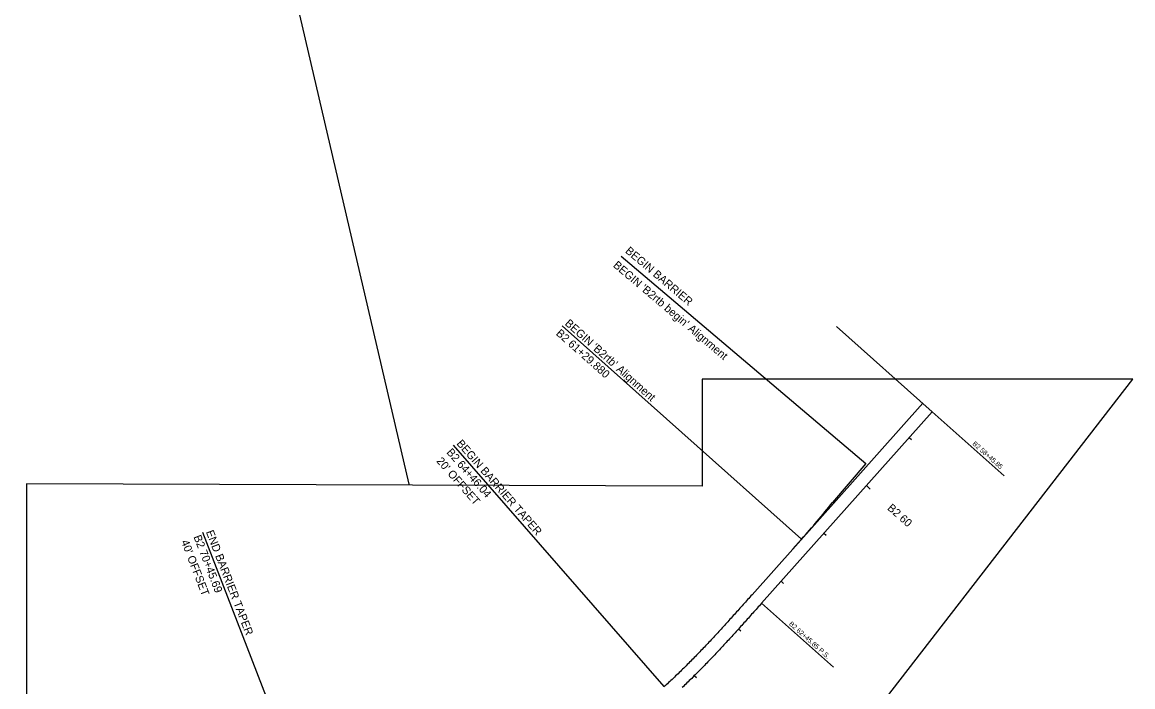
# Model space of a CAD drawing. Extents: x 7583978 to 7589962, y 550226 to 553847.
# Drawn here: x 7588230 to 7589962, y 550949 to 551985 of the extents above; entities that cross this region are included whole.
import ezdxf

# ---------------------------------------------------------------- set-up
doc = ezdxf.new("R2010")
doc.units = 0
for name, color, linetype in [('#plot_shape', 7, 'Continuous'), ('Default', 7, 'Continuous'), ('P_RDWY_ALIGN_Main', 7, 'Continuous'), ('P_RDWY_ALIGN_MainTx', 7, 'Continuous'), ('P_RDWY_ALIGN_Ramp', 7, 'Continuous'), ('P_RDWY_ALIGN_RampTic', 7, 'Continuous'), ('P_RDWY_ALIGN_RampTx', 7, 'Continuous')]:
    doc.layers.add(name, color=color, linetype=linetype)

msp = doc.modelspace()

# ---------------------------------------------------------------- linework, layer by layer
at = {"layer": '#plot_shape'}
msp.add_lwpolyline([(7588834, 551264.9), (7588256.1, 553744.3), (7587181.8, 553744.3)], dxfattribs=at)
msp.add_lwpolyline([(7588237.1, 551265.4), (7588237.1, 550226), (7589430.9, 550226), (7589430.9, 550741.5), (7589962.5, 551428.8), (7589291.1, 551428.4), (7589291.1, 551261.9)], close=True, dxfattribs=at)
at = {"layer": 'Default'}
for p, q in [((7589164.5, 551620.5), (7589546, 551297.3)), ((7589072.6, 551511.8), (7589445.8, 551179)), ((7589231.8, 550949.2), (7588902.8, 551325.7)), ((7588692.7, 550723.1), (7588512.2, 551189.4))]:
    msp.add_line(p, q, dxfattribs=at)
at = {"layer": 'P_RDWY_ALIGN_Main'}
for p, q in [((7589634.8, 551391), (7589368.6, 551092.5)), ((7589546, 551297.3), (7589494.2, 551236.2)), ((7589494.2, 551236.2), (7589494.1, 551236)), ((7589445.7, 551179), (7589432.4, 551164)), ((7589445.8, 551179), (7589445.7, 551179)), ((7589361.7, 551084.8), (7589360, 551082.9)), ((7589363.4, 551086.7), (7589361.7, 551084.8)), ((7589365.2, 551088.6), (7589363.4, 551086.7)), ((7589366.9, 551090.6), (7589365.2, 551088.6)), ((7589368.6, 551092.5), (7589366.9, 551090.6)), ((7589346.3, 551067.5), (7589344.6, 551065.6)), ((7589348, 551069.4), (7589346.3, 551067.5)), ((7589349.7, 551071.4), (7589348, 551069.4)), ((7589351.4, 551073.3), (7589349.7, 551071.4)), ((7589353.1, 551075.2), (7589351.4, 551073.3)), ((7589354.9, 551077.1), (7589353.1, 551075.2)), ((7589356.6, 551079), (7589354.9, 551077.1)), ((7589358.3, 551081), (7589356.6, 551079)), ((7589360, 551082.9), (7589358.3, 551081)), ((7589329.1, 551048.5), (7589327.3, 551046.6)), ((7589330.8, 551050.4), (7589329.1, 551048.5)), ((7589332.5, 551052.3), (7589330.8, 551050.4)), ((7589334.2, 551054.2), (7589332.5, 551052.3)), ((7589336, 551056.1), (7589334.2, 551054.2)), ((7589337.7, 551058), (7589336, 551056.1)), ((7589339.4, 551059.9), (7589337.7, 551058)), ((7589341.1, 551061.8), (7589339.4, 551059.9)), ((7589342.8, 551063.7), (7589341.1, 551061.8)), ((7589344.6, 551065.6), (7589342.8, 551063.7)), ((7589313.5, 551031.4), (7589311.8, 551029.6)), ((7589315.2, 551033.3), (7589313.5, 551031.4)), ((7589317, 551035.2), (7589315.2, 551033.3)), ((7589318.7, 551037.1), (7589317, 551035.2)), ((7589320.4, 551039), (7589318.7, 551037.1)), ((7589322.2, 551040.9), (7589320.4, 551039)), ((7589323.9, 551042.8), (7589322.2, 551040.9)), ((7589325.6, 551044.7), (7589323.9, 551042.8)), ((7589327.3, 551046.6), (7589325.6, 551044.7)), ((7589297.8, 551014.6), (7589296.1, 551012.8)), ((7589299.6, 551016.5), (7589297.8, 551014.6)), ((7589301.3, 551018.3), (7589299.6, 551016.5)), ((7589303.1, 551020.2), (7589301.3, 551018.3)), ((7589304.8, 551022.1), (7589303.1, 551020.2)), ((7589306.5, 551023.9), (7589304.8, 551022.1)), ((7589308.3, 551025.8), (7589306.5, 551023.9)), ((7589310, 551027.7), (7589308.3, 551025.8)), ((7589311.8, 551029.6), (7589310, 551027.7)), ((7589281.9, 550998), (7589280.2, 550996.2)), ((7589283.7, 550999.9), (7589281.9, 550998)), ((7589285.5, 551001.7), (7589283.7, 550999.9)), ((7589287.3, 551003.5), (7589285.5, 551001.7)), ((7589289, 551005.4), (7589287.3, 551003.5)), ((7589290.8, 551007.2), (7589289, 551005.4)), ((7589292.5, 551009.1), (7589290.8, 551007.2)), ((7589294.3, 551010.9), (7589292.5, 551009.1)), ((7589296.1, 551012.8), (7589294.3, 551010.9)), ((7589264.1, 550980), (7589262.3, 550978.2)), ((7589265.9, 550981.8), (7589264.1, 550980)), ((7589267.7, 550983.5), (7589265.9, 550981.8)), ((7589269.5, 550985.3), (7589267.7, 550983.5)), ((7589271.2, 550987.1), (7589269.5, 550985.3)), ((7589273, 550989), (7589271.2, 550987.1)), ((7589274.8, 550990.8), (7589273, 550989)), ((7589276.6, 550992.6), (7589274.8, 550990.8)), ((7589278.4, 550994.4), (7589276.6, 550992.6)), ((7589280.2, 550996.2), (7589278.4, 550994.4)), ((7589245.9, 550962.3), (7589244, 550960.5)), ((7589247.7, 550964), (7589245.9, 550962.3)), ((7589249.5, 550965.8), (7589247.7, 550964)), ((7589251.4, 550967.5), (7589249.5, 550965.8)), ((7589253.2, 550969.3), (7589251.4, 550967.5)), ((7589255, 550971.1), (7589253.2, 550969.3)), ((7589256.8, 550972.8), (7589255, 550971.1)), ((7589258.6, 550974.6), (7589256.8, 550972.8)), ((7589260.4, 550976.4), (7589258.6, 550974.6)), ((7589262.3, 550978.2), (7589260.4, 550976.4)), ((7589231.8, 550949.2), (7589231.2, 550948.6)), ((7589232.9, 550950.2), (7589231.8, 550949.2)), ((7589234.8, 550951.9), (7589232.9, 550950.2)), ((7589236.6, 550953.6), (7589234.8, 550951.9)), ((7589238.5, 550955.4), (7589236.6, 550953.6)), ((7589240.3, 550957.1), (7589238.5, 550955.4)), ((7589242.2, 550958.8), (7589240.3, 550957.1)), ((7589244, 550960.5), (7589242.2, 550958.8))]:
    msp.add_line(p, q, dxfattribs=at)
msp.add_arc((7588345, 552160.8), 1475, 318.2726, 321.1741, dxfattribs=at)
at = {"layer": 'P_RDWY_ALIGN_MainTx'}
for centre in [(7589634.8, 551391), (7589649.7, 551377.7), (7589546, 551297.3), (7589494.1, 551236), (7589494.2, 551236.2), (7589445.7, 551179), (7589445.8, 551179), (7589432.4, 551164), (7589361.7, 551084.8), (7589363.4, 551086.7), (7589365.2, 551088.6), (7589366.9, 551090.6), (7589368.6, 551092.5), (7589346.3, 551067.5), (7589348, 551069.4), (7589349.7, 551071.4), (7589351.4, 551073.3), (7589353.1, 551075.2), (7589354.9, 551077.1), (7589356.6, 551079), (7589358.3, 551081), (7589360, 551082.9), (7589383.5, 551079.2), (7589329.1, 551048.5), (7589330.8, 551050.4), (7589332.5, 551052.3), (7589334.2, 551054.2), (7589336, 551056.1), (7589337.7, 551058), (7589339.4, 551059.9), (7589341.1, 551061.8), (7589342.8, 551063.7), (7589344.6, 551065.6), (7589313.5, 551031.4), (7589315.2, 551033.3), (7589317, 551035.2), (7589318.7, 551037.1), (7589320.4, 551039), (7589322.2, 551040.9), (7589323.9, 551042.8), (7589325.6, 551044.7), (7589327.3, 551046.6), (7589297.8, 551014.6), (7589299.6, 551016.5), (7589301.3, 551018.3), (7589303.1, 551020.2), (7589304.8, 551022.1), (7589306.5, 551023.9), (7589308.3, 551025.8), (7589310, 551027.7), (7589311.8, 551029.6), (7589281.9, 550998), (7589283.7, 550999.9), (7589285.5, 551001.7), (7589287.3, 551003.5), (7589289, 551005.4), (7589290.8, 551007.2), (7589292.5, 551009.1), (7589294.3, 551010.9), (7589296.1, 551012.8), (7589264.1, 550980), (7589265.9, 550981.8), (7589267.7, 550983.5), (7589269.5, 550985.3), (7589271.2, 550987.1), (7589273, 550989), (7589274.8, 550990.8), (7589276.6, 550992.6), (7589278.4, 550994.4), (7589280.2, 550996.2), (7589245.9, 550962.3), (7589247.7, 550964), (7589249.5, 550965.8), (7589251.4, 550967.5), (7589253.2, 550969.3), (7589255, 550971.1), (7589256.8, 550972.8), (7589258.6, 550974.6), (7589260.4, 550976.4), (7589262.3, 550978.2), (7589231.8, 550949.2), (7589232.9, 550950.2), (7589234.8, 550951.9), (7589236.6, 550953.6), (7589238.5, 550955.4), (7589240.3, 550957.1), (7589242.2, 550958.8), (7589244, 550960.5)]:
    msp.add_circle(centre, 0.00187, dxfattribs=at)
at = {"layer": 'P_RDWY_ALIGN_Ramp'}
msp.add_line((7589649.7, 551377.7), (7589383.5, 551079.2), dxfattribs=at)
msp.add_lwpolyline([(7589383.5, 551079.2), (7589381.8, 551077.3), (7589380.1, 551075.3), (7589378.4, 551073.4), (7589376.6, 551071.5), (7589374.9, 551069.6), (7589373.2, 551067.6), (7589371.5, 551065.7), (7589369.8, 551063.8), (7589368, 551061.9), (7589366.3, 551059.9), (7589364.6, 551058), (7589362.9, 551056.1), (7589361.2, 551054.2), (7589359.4, 551052.2), (7589357.7, 551050.3), (7589356, 551048.4), (7589354.3, 551046.5), (7589352.5, 551044.6), (7589350.8, 551042.7), (7589349.1, 551040.7), (7589347.3, 551038.8), (7589345.6, 551036.9), (7589343.9, 551035), (7589342.1, 551033.1), (7589340.4, 551031.2), (7589338.7, 551029.3), (7589336.9, 551027.4), (7589335.2, 551025.5), (7589333.4, 551023.6), (7589331.7, 551021.7), (7589329.9, 551019.8), (7589328.2, 551017.9), (7589326.4, 551016), (7589324.7, 551014.1), (7589322.9, 551012.2), (7589321.2, 551010.3), (7589319.4, 551008.4), (7589317.7, 551006.5), (7589315.9, 551004.7), (7589314.1, 551002.8), (7589312.3, 551000.9), (7589310.6, 550999), (7589308.8, 550997.1), (7589307, 550995.3), (7589305.2, 550993.4), (7589303.5, 550991.5), (7589301.7, 550989.7), (7589299.9, 550987.8), (7589298.1, 550986), (7589296.3, 550984.1), (7589294.5, 550982.3), (7589292.7, 550980.4), (7589290.9, 550978.6), (7589289.1, 550976.7), (7589287.3, 550974.9), (7589285.4, 550973.1), (7589283.6, 550971.2), (7589281.8, 550969.4), (7589280, 550967.6), (7589278.1, 550965.8), (7589276.3, 550963.9), (7589274.5, 550962.1), (7589272.6, 550960.3), (7589270.8, 550958.5), (7589268.9, 550956.7), (7589267.1, 550954.9), (7589265.2, 550953.1), (7589263.4, 550951.3), (7589261.5, 550949.6), (7589259.6, 550947.8)], dxfattribs=at)
at = {"layer": 'P_RDWY_ALIGN_RampTic'}
for points in [[(7589617.4, 551334), (7589613.7, 551337.3)], [(7589553.1, 551257.3), (7589547.1, 551262.7)], [(7589484.3, 551184.7), (7589480.6, 551188)], [(7589417.8, 551110.1), (7589414, 551113.4)], [(7589351.1, 551035.5), (7589347.4, 551038.9)], [(7589282.2, 550962.7), (7589278.6, 550966.2)]]:
    msp.add_lwpolyline(points, dxfattribs=at)
at = {"layer": 'P_RDWY_ALIGN_RampTx'}
for points in [[(7589649.7, 551377.7), (7589500.5, 551510.8)], [(7589649.7, 551377.7), (7589761.7, 551277.9)], [(7589383.5, 551079.2), (7589495.5, 550979.3)]]:
    msp.add_lwpolyline(points, dxfattribs=at)

# ---------------------------------------------------------------- texts
at = {"layer": 'Default'}
for s, rotation, p in [('BEGIN BARRIER', 319.7247, (7589169.9, 551626.9)), ("BEGIN 'B2rtb begin' Alignment", 319.7247, (7589151, 551604.6)), ("BEGIN 'B2rtb' Alignment", 318.2726, (7589075.7, 551514.1)), ('B2 61+29.880', 318.2726, (7589061.9, 551498.6)), ('BEGIN BARRIER TAPER', 311.1496, (7588907, 551327.7)), ('B2 64+46.04', 311.1496, (7588891.3, 551314)), ("20' OFFSET", 311.1496, (7588875.6, 551300.4)), ('END BARRIER TAPER', 291.1549, (7588516.7, 551190.4)), ("40' OFFSET", 291.1549, (7588477.9, 551175.3)), ('B2 70+45.69', 291.1549, (7588497.3, 551182.8))]:
    msp.add_text(s, height=12.48, rotation=rotation, dxfattribs=at).set_placement(p)
at = {"layer": 'P_RDWY_ALIGN_RampTic'}
msp.add_text('B2 60', height=12.5, rotation=318.2735, dxfattribs=at).set_placement((7589578.7, 551226.2))
at = {"layer": 'P_RDWY_ALIGN_RampTx'}
for s, height, rotation, p in [('Ah. B2 58+45.85', 0.00625, 138.2735, (7589501.3, 551510.1)), ('Bk. 58+45.85', 0.00625, 138.2735, (7589501.3, 551510.1)), ('B2 58+45.85 ', 7.5, 318.2735, (7589711.7, 551327)), ('B2 62+45.85 P.S. ', 7.5, 318.2735, (7589425.5, 551046.1))]:
    msp.add_text(s, height=height, rotation=rotation, dxfattribs=at).set_placement(p)

doc.saveas('drawing.dxf')
